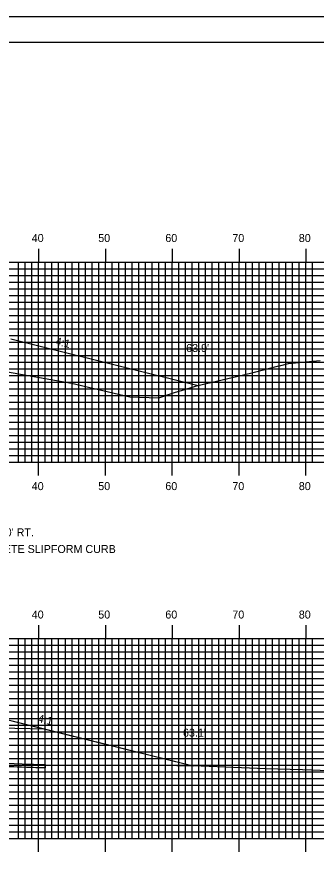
# Model space of a CAD drawing. Extents: x 1754708 to 1755051, y 442591 to 442811.
# Drawn here: x 1754910.3 to 1754955.1, y 442684.8 to 442810.5 of the extents above; entities that cross this region are included whole.
import ezdxf

# ---------------------------------------------------------------- set-up
doc = ezdxf.new("R2010")
doc.units = 0
for name, color, linetype in [('ANNOTATION', 7, 'Continuous'), ('BORDER', 7, 'Continuous'), ('D_Roadway_SlopeLines', 7, 'Continuous'), ('D_Roadway_SubGrade', 7, 'Continuous'), ('D_Text_Standard', 7, 'Continuous'), ('DIMENSIONS', 7, 'Continuous'), ('GRUBBING IN FILL', 7, 'Continuous'), ('H_V ANNOTATION', 7, 'Continuous'), ('MAJOR', 7, 'Continuous'), ('MINOR', 7, 'Continuous'), ('PLOT BOUNDARY', 7, 'Continuous'), ('S_Roadway_Centerline', 7, 'Continuous')]:
    doc.layers.add(name, color=color, linetype=linetype)

msp = doc.modelspace()

# ---------------------------------------------------------------- linework, layer by layer
at = {"layer": 'BORDER'}
msp.add_lwpolyline([(1754723.92, 442596.67), (1755043.92, 442596.67), (1755043.92, 442806.67), (1754723.92, 442806.67)], close=True, dxfattribs=at)
at = {"layer": 'D_Roadway_SlopeLines'}
for p, q in [((1754909.37, 442762.24), (1754913.37, 442761.24)), ((1754913.37, 442761.24), (1754937.38, 442755.24))]:
    msp.add_line(p, q, dxfattribs=at)
msp.add_lwpolyline([(1754904.32, 442706.29), (1754916.32, 442703.29), (1754936.68, 442698.24)], dxfattribs=at)
at = {"layer": 'D_Roadway_SubGrade'}
msp.add_lwpolyline([(1754896.32, 442705.94), (1754896.32, 442706.36), (1754904.32, 442706.04), (1754904.32, 442706.29), (1754914.49, 442703.74), (1754896.32, 442704.11)], close=True, dxfattribs=at)
at = {"layer": 'DIMENSIONS'}
msp.add_line((1754904.32, 442706.29), (1754936.68, 442698.24), dxfattribs=at)
at = {"layer": 'GRUBBING IN FILL'}
msp.add_line((1754914.49, 442698.4), (1754914.49, 442697.9), dxfattribs=at)
msp.add_line((1754914.49, 442698.4), (1754914.49, 442697.9), dxfattribs=at)
msp.add_lwpolyline([(1754843.34, 442701.66), (1754848.87, 442700.48), (1754852.11, 442699.76), (1754854.17, 442698.98), (1754857.62, 442698.75), (1754875.22, 442699.4), (1754875.98, 442699.45), (1754878.89, 442699.33), (1754896.03, 442698.63), (1754900.07, 442698.61), (1754907.45, 442698.16), (1754914.49, 442697.9)], dxfattribs=at)
msp.add_lwpolyline([(1754843.34, 442701.66), (1754848.87, 442700.48), (1754852.11, 442699.76), (1754854.17, 442698.98), (1754857.62, 442698.75), (1754875.22, 442699.4), (1754875.98, 442699.45), (1754878.89, 442699.33), (1754896.03, 442698.63), (1754900.07, 442698.61), (1754907.45, 442698.16), (1754914.49, 442697.9)], dxfattribs=at)
msp.add_lwpolyline([(1754873.52, 442699.84), (1754875.19, 442699.9), (1754875.98, 442699.95), (1754877.44, 442699.89), (1754878.91, 442699.83), (1754887.48, 442699.48), (1754896.04, 442699.13), (1754900.09, 442699.11), (1754903.78, 442698.88), (1754907.48, 442698.65), (1754911.04, 442698.52), (1754914.49, 442698.4), (1754914.49, 442697.9), (1754910.97, 442698.03), (1754907.45, 442698.16), (1754903.76, 442698.38), (1754900.07, 442698.61), (1754896.03, 442698.63), (1754887.46, 442698.98), (1754878.89, 442699.33), (1754875.98, 442699.45), (1754873.52, 442699.34)], close=True, dxfattribs=at)
msp.add_lwpolyline([(1754873.52, 442699.84), (1754875.19, 442699.9), (1754875.98, 442699.95), (1754877.44, 442699.89), (1754878.91, 442699.83), (1754887.48, 442699.48), (1754896.04, 442699.13), (1754900.09, 442699.11), (1754903.78, 442698.88), (1754907.48, 442698.65), (1754911.04, 442698.52), (1754914.49, 442698.4), (1754914.49, 442697.9), (1754910.97, 442698.03), (1754907.45, 442698.16), (1754903.76, 442698.38), (1754900.07, 442698.61), (1754896.03, 442698.63), (1754887.46, 442698.98), (1754878.89, 442699.33), (1754875.98, 442699.45), (1754873.52, 442699.34)], close=True, dxfattribs=at)
at = {"layer": 'MAJOR'}
for p, q in [((1754913.52, 442775.77), (1754913.52, 442773.77)), ((1754923.52, 442775.77), (1754923.52, 442773.77)), ((1754933.52, 442775.77), (1754933.52, 442773.77)), ((1754943.52, 442775.77), (1754943.52, 442773.77)), ((1754953.52, 442775.77), (1754953.52, 442773.77)), ((1754733.52, 442773.77), (1755013.52, 442773.77)), ((1754733.52, 442773.77), (1755013.52, 442773.77)), ((1754913.52, 442743.77), (1754913.52, 442773.77)), ((1754923.52, 442743.77), (1754923.52, 442773.77)), ((1754933.52, 442743.77), (1754933.52, 442773.77)), ((1754943.52, 442743.77), (1754943.52, 442773.77)), ((1754953.52, 442743.77), (1754953.52, 442773.77)), ((1754733.52, 442768.77), (1755013.52, 442768.77)), ((1754733.52, 442763.77), (1755013.52, 442763.77)), ((1754733.52, 442758.77), (1755013.52, 442758.77)), ((1754733.52, 442753.77), (1755013.52, 442753.77)), ((1754733.52, 442748.77), (1755013.52, 442748.77)), ((1754733.52, 442743.77), (1755013.52, 442743.77)), ((1754733.52, 442743.77), (1755013.52, 442743.77)), ((1754913.52, 442741.77), (1754913.52, 442743.77)), ((1754923.52, 442741.77), (1754923.52, 442743.77)), ((1754933.52, 442741.77), (1754933.52, 442743.77)), ((1754943.52, 442741.77), (1754943.52, 442743.77)), ((1754953.52, 442741.77), (1754953.52, 442743.77)), ((1754913.52, 442719.32), (1754913.52, 442717.31)), ((1754923.52, 442719.32), (1754923.52, 442717.31)), ((1754933.52, 442719.32), (1754933.52, 442717.31)), ((1754943.52, 442719.32), (1754943.52, 442717.31)), ((1754953.52, 442719.32), (1754953.52, 442717.31)), ((1754733.52, 442717.31), (1755013.52, 442717.31)), ((1754733.52, 442717.31), (1755013.52, 442717.31)), ((1754913.52, 442687.31), (1754913.52, 442717.31)), ((1754923.52, 442687.31), (1754923.52, 442717.31)), ((1754933.52, 442687.31), (1754933.52, 442717.31)), ((1754943.52, 442687.31), (1754943.52, 442717.31)), ((1754953.52, 442687.31), (1754953.52, 442717.31)), ((1754733.52, 442712.31), (1755013.52, 442712.31)), ((1754733.52, 442707.31), (1755013.52, 442707.31)), ((1754733.52, 442702.31), (1755013.52, 442702.31)), ((1754733.52, 442697.31), (1755013.52, 442697.31)), ((1754733.52, 442692.31), (1755013.52, 442692.31)), ((1754733.52, 442687.31), (1755013.52, 442687.31)), ((1754733.52, 442687.31), (1755013.52, 442687.31)), ((1754913.52, 442685.31), (1754913.52, 442687.31)), ((1754923.52, 442685.31), (1754923.52, 442687.31)), ((1754933.52, 442685.31), (1754933.52, 442687.31)), ((1754943.52, 442685.31), (1754943.52, 442687.31)), ((1754953.52, 442685.31), (1754953.52, 442687.31))]:
    msp.add_line(p, q, dxfattribs=at)
at = {"layer": 'MINOR'}
for p, q in [((1754733.52, 442772.77), (1755013.52, 442772.77)), ((1754910.52, 442743.77), (1754910.52, 442773.77)), ((1754911.52, 442743.77), (1754911.52, 442773.77)), ((1754912.52, 442743.77), (1754912.52, 442773.77)), ((1754914.52, 442743.77), (1754914.52, 442773.77)), ((1754915.52, 442743.77), (1754915.52, 442773.77)), ((1754916.52, 442743.77), (1754916.52, 442773.77)), ((1754917.52, 442743.77), (1754917.52, 442773.77)), ((1754918.52, 442743.77), (1754918.52, 442773.77)), ((1754919.52, 442743.77), (1754919.52, 442773.77)), ((1754920.52, 442743.77), (1754920.52, 442773.77)), ((1754921.52, 442743.77), (1754921.52, 442773.77)), ((1754922.52, 442743.77), (1754922.52, 442773.77)), ((1754924.52, 442743.77), (1754924.52, 442773.77)), ((1754925.52, 442743.77), (1754925.52, 442773.77)), ((1754926.52, 442743.77), (1754926.52, 442773.77)), ((1754927.52, 442743.77), (1754927.52, 442773.77)), ((1754928.52, 442743.77), (1754928.52, 442773.77)), ((1754929.52, 442743.77), (1754929.52, 442773.77)), ((1754930.52, 442743.77), (1754930.52, 442773.77)), ((1754931.52, 442743.77), (1754931.52, 442773.77)), ((1754932.52, 442743.77), (1754932.52, 442773.77)), ((1754934.52, 442743.77), (1754934.52, 442773.77)), ((1754935.52, 442743.77), (1754935.52, 442773.77)), ((1754936.52, 442743.77), (1754936.52, 442773.77)), ((1754937.52, 442743.77), (1754937.52, 442773.77)), ((1754938.52, 442743.77), (1754938.52, 442773.77)), ((1754939.52, 442743.77), (1754939.52, 442773.77)), ((1754940.52, 442743.77), (1754940.52, 442773.77)), ((1754941.52, 442743.77), (1754941.52, 442773.77)), ((1754942.52, 442743.77), (1754942.52, 442773.77)), ((1754944.52, 442743.77), (1754944.52, 442773.77)), ((1754945.52, 442743.77), (1754945.52, 442773.77)), ((1754946.52, 442743.77), (1754946.52, 442773.77)), ((1754947.52, 442743.77), (1754947.52, 442773.77)), ((1754948.52, 442743.77), (1754948.52, 442773.77)), ((1754949.52, 442743.77), (1754949.52, 442773.77)), ((1754950.52, 442743.77), (1754950.52, 442773.77)), ((1754951.52, 442743.77), (1754951.52, 442773.77)), ((1754952.52, 442743.77), (1754952.52, 442773.77)), ((1754954.52, 442743.77), (1754954.52, 442773.77)), ((1754733.52, 442771.77), (1755013.52, 442771.77)), ((1754733.52, 442770.77), (1755013.52, 442770.77)), ((1754733.52, 442769.77), (1755013.52, 442769.77)), ((1754733.52, 442767.77), (1755013.52, 442767.77)), ((1754733.52, 442766.77), (1755013.52, 442766.77)), ((1754733.52, 442765.77), (1755013.52, 442765.77)), ((1754733.52, 442764.77), (1755013.52, 442764.77)), ((1754733.52, 442762.77), (1755013.52, 442762.77)), ((1754733.52, 442761.77), (1755013.52, 442761.77)), ((1754733.52, 442760.77), (1755013.52, 442760.77)), ((1754733.52, 442759.77), (1755013.52, 442759.77)), ((1754733.52, 442757.77), (1755013.52, 442757.77)), ((1754733.52, 442756.77), (1755013.52, 442756.77)), ((1754733.52, 442755.77), (1755013.52, 442755.77)), ((1754733.52, 442754.77), (1755013.52, 442754.77)), ((1754733.52, 442752.77), (1755013.52, 442752.77)), ((1754733.52, 442751.77), (1755013.52, 442751.77)), ((1754733.52, 442750.77), (1755013.52, 442750.77)), ((1754733.52, 442749.77), (1755013.52, 442749.77)), ((1754733.52, 442747.77), (1755013.52, 442747.77)), ((1754733.52, 442746.77), (1755013.52, 442746.77)), ((1754733.52, 442745.77), (1755013.52, 442745.77)), ((1754733.52, 442744.77), (1755013.52, 442744.77)), ((1754910.52, 442687.31), (1754910.52, 442717.31)), ((1754911.52, 442687.31), (1754911.52, 442717.31)), ((1754912.52, 442687.31), (1754912.52, 442717.31)), ((1754914.52, 442687.31), (1754914.52, 442717.31)), ((1754915.52, 442687.31), (1754915.52, 442717.31)), ((1754916.52, 442687.31), (1754916.52, 442717.31)), ((1754917.52, 442687.31), (1754917.52, 442717.31)), ((1754918.52, 442687.31), (1754918.52, 442717.31)), ((1754919.52, 442687.31), (1754919.52, 442717.31)), ((1754920.52, 442687.31), (1754920.52, 442717.31)), ((1754921.52, 442687.31), (1754921.52, 442717.31)), ((1754922.52, 442687.31), (1754922.52, 442717.31)), ((1754924.52, 442687.31), (1754924.52, 442717.31)), ((1754925.52, 442687.31), (1754925.52, 442717.31)), ((1754926.52, 442687.31), (1754926.52, 442717.31)), ((1754927.52, 442687.31), (1754927.52, 442717.31)), ((1754928.52, 442687.31), (1754928.52, 442717.31)), ((1754929.52, 442687.31), (1754929.52, 442717.31)), ((1754930.52, 442687.31), (1754930.52, 442717.31)), ((1754931.52, 442687.31), (1754931.52, 442717.31)), ((1754932.52, 442687.31), (1754932.52, 442717.31)), ((1754934.52, 442687.31), (1754934.52, 442717.31)), ((1754935.52, 442687.31), (1754935.52, 442717.31)), ((1754936.52, 442687.31), (1754936.52, 442717.31)), ((1754937.52, 442687.31), (1754937.52, 442717.31)), ((1754938.52, 442687.31), (1754938.52, 442717.31)), ((1754939.52, 442687.31), (1754939.52, 442717.31)), ((1754940.52, 442687.31), (1754940.52, 442717.31)), ((1754941.52, 442687.31), (1754941.52, 442717.31)), ((1754942.52, 442687.31), (1754942.52, 442717.31)), ((1754944.52, 442687.31), (1754944.52, 442717.31)), ((1754945.52, 442687.31), (1754945.52, 442717.31)), ((1754946.52, 442687.31), (1754946.52, 442717.31)), ((1754947.52, 442687.31), (1754947.52, 442717.31)), ((1754948.52, 442687.31), (1754948.52, 442717.31)), ((1754949.52, 442687.31), (1754949.52, 442717.31)), ((1754950.52, 442687.31), (1754950.52, 442717.31)), ((1754951.52, 442687.31), (1754951.52, 442717.31)), ((1754952.52, 442687.31), (1754952.52, 442717.31)), ((1754954.52, 442687.31), (1754954.52, 442717.31)), ((1754733.52, 442716.31), (1755013.52, 442716.31)), ((1754733.52, 442715.31), (1755013.52, 442715.31)), ((1754733.52, 442714.31), (1755013.52, 442714.31)), ((1754733.52, 442713.31), (1755013.52, 442713.31)), ((1754733.52, 442711.31), (1755013.52, 442711.31)), ((1754733.52, 442710.31), (1755013.52, 442710.31)), ((1754733.52, 442709.31), (1755013.52, 442709.31)), ((1754733.52, 442708.31), (1755013.52, 442708.31)), ((1754733.52, 442706.31), (1755013.52, 442706.31)), ((1754733.52, 442705.31), (1755013.52, 442705.31)), ((1754733.52, 442704.31), (1755013.52, 442704.31)), ((1754733.52, 442703.31), (1755013.52, 442703.31)), ((1754733.52, 442701.31), (1755013.52, 442701.31)), ((1754733.52, 442700.31), (1755013.52, 442700.31)), ((1754733.52, 442699.31), (1755013.52, 442699.31)), ((1754733.52, 442698.31), (1755013.52, 442698.31)), ((1754733.52, 442696.31), (1755013.52, 442696.31)), ((1754733.52, 442695.31), (1755013.52, 442695.31)), ((1754733.52, 442694.31), (1755013.52, 442694.31)), ((1754733.52, 442693.31), (1755013.52, 442693.31)), ((1754733.52, 442691.31), (1755013.52, 442691.31)), ((1754733.52, 442690.31), (1755013.52, 442690.31)), ((1754733.52, 442689.31), (1755013.52, 442689.31)), ((1754733.52, 442688.31), (1755013.52, 442688.31))]:
    msp.add_line(p, q, dxfattribs=at)
at = {"layer": 'PLOT BOUNDARY'}
msp.add_lwpolyline([(1754707.73, 442590.55), (1755047.73, 442590.55), (1755047.73, 442810.55), (1754707.73, 442810.55)], close=True, dxfattribs=at)
at = {"layer": 'S_Roadway_Centerline'}
for points in [[(1754827.27, 442763.43), (1754829.88, 442764.43), (1754833.2, 442765.41), (1754836.39, 442766.33), (1754840.04, 442767.27), (1754841.51, 442767.56), (1754850.9, 442768.09), (1754852.16, 442768.1), (1754853.03, 442768.02), (1754869.52, 442764.6), (1754876.27, 442763.75), (1754887.31, 442761.72), (1754900.38, 442758.92), (1754908.03, 442757.43), (1754918.44, 442755.61), (1754927.18, 442753.58), (1754931.54, 442753.43)], [(1754931.54, 442753.43), (1754933.24, 442754.01), (1754933.87, 442754.23), (1754935.05, 442754.58), (1754935.72, 442754.77), (1754936.87, 442755.12), (1754937.14, 442755.19), (1754944, 442756.79), (1754945.86, 442757.27), (1754949.3, 442758.14), (1754949.76, 442758.25), (1754950.94, 442758.55), (1754955.68, 442759.02)], [(1754820.81, 442707.13), (1754822.85, 442706.77), (1754825.07, 442706.33), (1754826.52, 442706.04), (1754828.08, 442705.98), (1754832.68, 442704.45), (1754848.97, 442700.97), (1754852.26, 442700.24), (1754854.27, 442699.47), (1754857.63, 442699.25), (1754875.19, 442699.9), (1754875.98, 442699.95), (1754878.91, 442699.83), (1754896.04, 442699.13), (1754900.09, 442699.11), (1754907.48, 442698.65), (1754914.61, 442698.39), (1754927.56, 442698.33), (1754934.19, 442698.29), (1754935.53, 442698.26), (1754937.83, 442698.21), (1754947.48, 442697.84), (1754953.04, 442697.65), (1754970.33, 442697)]]:
    msp.add_lwpolyline(points, dxfattribs=at)

# ---------------------------------------------------------------- texts
at = {"layer": 'ANNOTATION'}
for p in [(1754915.93, 442761.37), (1754913.31, 442704.8)]:
    msp.add_text('4:1', height=1.2, rotation=346.9159, dxfattribs=at).set_placement(p)
at = {"layer": 'D_Text_Standard'}
for s, p in [("63.9'", (1754935.61, 442760.28)), ("TO STA. 50+50.00, 32.0' RT.", (1754892.04, 442732.64)), ("INSTALL 215' CONCRETE SLIPFORM CURB", (1754892.04, 442730.14)), ("63.1'", (1754935.13, 442702.59))]:
    msp.add_text(s, height=1.2, dxfattribs=at).set_placement(p)
at = {"layer": 'H_V ANNOTATION'}
for s, p in [('40', (1754912.49, 442776.77)), ('50', (1754922.45, 442776.77)), ('60', (1754932.49, 442776.77)), ('70', (1754942.52, 442776.77)), ('80', (1754952.47, 442776.77)), ('40', (1754912.49, 442739.57)), ('50', (1754922.45, 442739.57)), ('60', (1754932.49, 442739.57)), ('70', (1754942.52, 442739.57)), ('80', (1754952.47, 442739.57)), ('40', (1754912.49, 442720.31)), ('50', (1754922.45, 442720.31)), ('60', (1754932.49, 442720.31)), ('70', (1754942.52, 442720.31)), ('80', (1754952.47, 442720.31))]:
    msp.add_text(s, height=1.2, dxfattribs=at).set_placement(p)

doc.saveas('drawing.dxf')
